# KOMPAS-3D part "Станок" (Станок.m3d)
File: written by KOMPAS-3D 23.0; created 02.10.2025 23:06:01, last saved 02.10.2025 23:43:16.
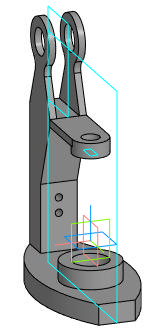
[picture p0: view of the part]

Document properties: Автор: Inspektor_Kot; Полное имя файла: C:\Users\Lost\Downloads\Telegram Desktop\ИМ-ИТ ЦД\ИМ-ИТ ЦД\Вариант 10\Станок.m3d

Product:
- Body: Тело 1
    Масса: 0.436767
- Body: Тело 2
    Масса: 9.74707
- Part/product: Станок
    Масса: 10.183837

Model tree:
1. Смещенная плоскость:1  (with: Элемент вращения:1)
     Расстояние = -45
2. Эскиз:3  (with: Фаска:1)
3. Элемент выдавливания:1
     Расстояние 1 = 20
4. Эскиз:4  (with: Элемент выдавливания:1)
5. Элемент выдавливания:2
     Расстояние 2 = 10
6. Эскиз:5  (with: Элемент выдавливания:2)
7. Элемент выдавливания:3
     Толщина стенки 1 = 83; Расстояние 2 = 48
8. Средняя плоскость:1  (with: Элемент выдавливания:3)
9. Эскиз:6  (with: Элемент выдавливания:3)
10. Элемент выдавливания:4
     Расстояние 1 = 30
11. Эскиз:7  (with: Элемент выдавливания:3)
12. Элемент выдавливания:5  (with: Элемент выдавливания:3)
     Расстояние 1 = -27
13. Эскиз:8  (with: Элемент выдавливания:3, Элемент выдавливания:1)
14. Элемент выдавливания:6
     Расстояние 1 = 25
15. Эскиз:9  (with: Элемент выдавливания:3)
16. Элемент выдавливания:7
     Расстояние 2 = 20
17. Эскиз:10  (with: Элемент выдавливания:3)
18. Элемент выдавливания:8
19. Эскиз:11  (with: Элемент выдавливания:3)
20. Элемент выдавливания:9
     Расстояние 2 = 9
21. Средняя плоскость:2  (with: Элемент выдавливания:4)
22. Зеркальный массив:1
23. Экземпляр ( 1 )
24. Экземпляр ( 2 )  (with: Элемент выдавливания:9)
25. Скругление:1  (with: Элемент выдавливания:9)
     Радиус = 14

Referenced files in I:\Autodesk Inventor Projects\ИМ-ИТ ЦД\Вариант 10\: Прибор контроля заготовок..a3d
